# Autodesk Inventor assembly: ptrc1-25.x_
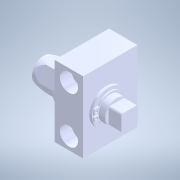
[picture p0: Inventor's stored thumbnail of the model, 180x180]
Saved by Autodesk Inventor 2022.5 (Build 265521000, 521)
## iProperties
Created: 2023-04
Part Number: ptrc1-25.x_
Document SubType Name: Assembly
Designer: ImaoCorp
Sending System: SOLIDWORKS 2021-2021301
MC: AMD64
MC_MODEL: Intel64 Family 6 Model 60 Stepping 3, GenuineIntel
OS: Windows_NT
FRU: Parasolid Version 32.1, build 255,  1- 1-2021
FORMAT: text
GUISE: transmit
KEY: ptrc1-25
FILE: ptrc1-25.x_t
DATE: Fri Apr  7 10:54:36 2023
Author: ImaoCorp
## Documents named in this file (3)
- X:\14_SW2022-Inv2022\00_全2023-1023新製品(TCC)まで\p\ptrc1-25\PTRC1-25.iam
- X:\14_SW2022-Inv2022\00_全2023-1023新製品(TCC)まで\p\ptrc1-25\ptrc1-25_01.ipt
- X:\14_SW2022-Inv2022\00_全2023-1023新製品(TCC)まで\p\ptrc1-25\ptrc1-25_02.ipt
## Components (2 placed, 2 different names)
1. ptrc1-25_01
2. ptrc1-25_02
